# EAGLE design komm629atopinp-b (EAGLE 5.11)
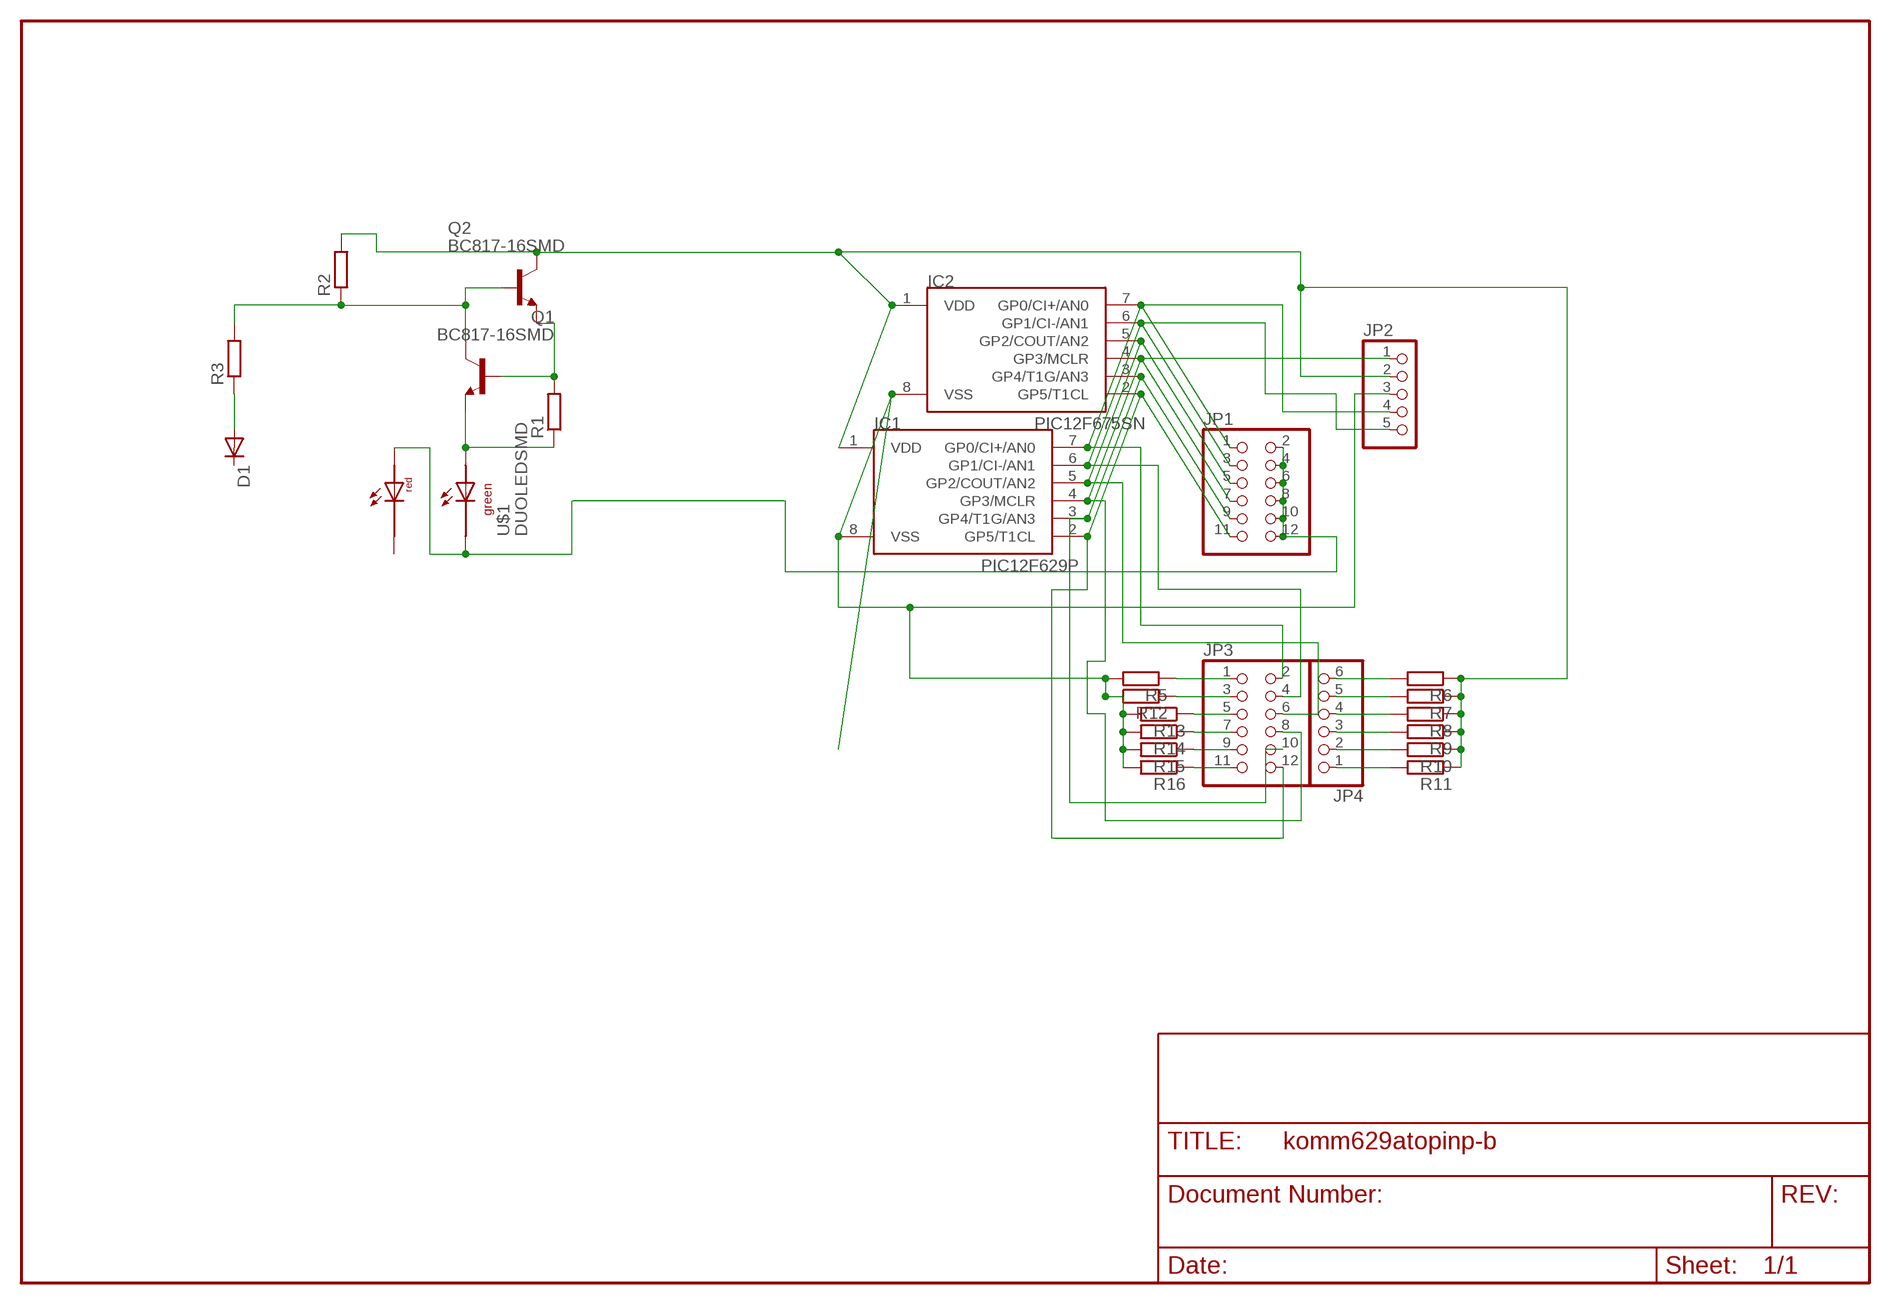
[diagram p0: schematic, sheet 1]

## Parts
D1  DIODE-MINIMELF  [MINIMELF]
IC1  PIC12F629P  [DIL8]
IC2  PIC12F675SN  [SO-08]
JP1  PINHD-2X6  [2X06]
JP2  PINHD-1X5  [1X05]
JP3  PINHD-2X6  [2X06]
JP4  PINHD-1X6  [1X06]
Q1  BC817-16SMD  [SOT23-BEC]
Q2  BC817-16SMD  [SOT23-BEC]
R1  R-EU_R1206  [R1206]
R2  R-EU_R1206  [R1206]
R3  R-EU_R1206  [R1206]
R5  R-EU_R1206  [R1206]
R6  R-EU_R1206  [R1206]
R7  R-EU_R1206  [R1206]
R8  R-EU_R1206  [R1206]
R9  R-EU_R1206  [R1206]
R10  R-EU_R1206  [R1206]
R11  R-EU_R1206  [R1206]
R12  R-EU_R1206  [R1206]
R13  R-EU_R1206  [R1206]
R14  R-EU_R1206  [R1206]
R15  R-EU_R1206  [R1206]
R16  R-EU_R1206  [R1206]
U$1  DUOLEDSMD  [DUOLEDSMD]

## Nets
N$1: IC1.3(GP4/T1G/AN3) IC2.3(GP4/T1G/AN3) JP1.9 JP3.10
N$2: Q1.E R1.1 U$1.AGRN
N$3: Q1.B Q2.E R1.2
N$4: JP1.2 JP1.4 JP1.6 JP1.8 JP1.10 JP1.12 U$1.ARED U$1.CGRN
N$5: IC1.8(VSS) IC2.8(VSS) JP2.3 R5.2 R12.2 R13.2 R14.2 R15.2 R16.2
N$6: IC1.1(VDD) IC2.1(VDD) JP2.2 Q2.C R2.2 R6.1 R7.1 R8.1 R9.1 R10.1 R11.1
N$7: Q1.C Q2.B R2.1 R3.2
N$8: D1.A R3.1
N$9: IC1.2(GP5/T1CL) IC2.2(GP5/T1CL) JP1.11 JP3.12
N$11: IC1.4(GP3/MCLR) IC2.4(GP3/MCLR) JP1.7 JP2.1 JP3.8
N$12: IC1.5(GP2/COUT/AN2) IC2.5(GP2/COUT/AN2) JP1.5 JP3.6
N$13: IC1.6(GP1/CI-/AN1) IC2.6(GP1/CI-/AN1) JP1.3 JP2.5 JP3.4
N$14: IC1.7(GP0/CI+/AN0) IC2.7(GP0/CI+/AN0) JP1.1 JP2.4 JP3.2
N$15: JP4.6 R6.2
N$18: JP3.1 R5.1
N$21: JP3.3 R12.1
N$22: JP3.5 R13.1
N$23: JP3.7 R14.1
N$24: JP3.9 R15.1
N$25: JP3.11 R16.1
N$26: JP4.5 R7.2
N$27: JP4.4 R8.2
N$28: JP4.3 R9.2
N$29: JP4.2 R10.2
N$30: JP4.1 R11.2
Unconnected: D1.C U$1.CRED

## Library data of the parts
D1 = diode:DIODE-: DIODE
IC1 IC2 = microchip-5:PIC12F6*: uPC nW 1k Program Flash memory 2x Timer Comparator 10b A/D converter/ 4xIN
JP1 JP3 = pinhead(2):PINHD-2X6: PIN HEADER
JP2 = pinhead:PINHD-1X5: PIN HEADER
JP4 = pinhead(2):PINHD-1X6: PIN HEADER
Q1 Q2 = transistor-npn:BC817*: NPN Transistor
R1-R3 = rcl:R-EU_: RESISTOR, European symbol
R5-R16 = rcl-2:R-EU_: RESISTOR, European symbol
U$1 = led:DUOLEDSMD

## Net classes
0 default: width 0.3 mm, drill 0.6 mm, clearance 0.2 mm
1 power: width 0.4 mm, drill 0.6 mm, clearance 0.2 mm

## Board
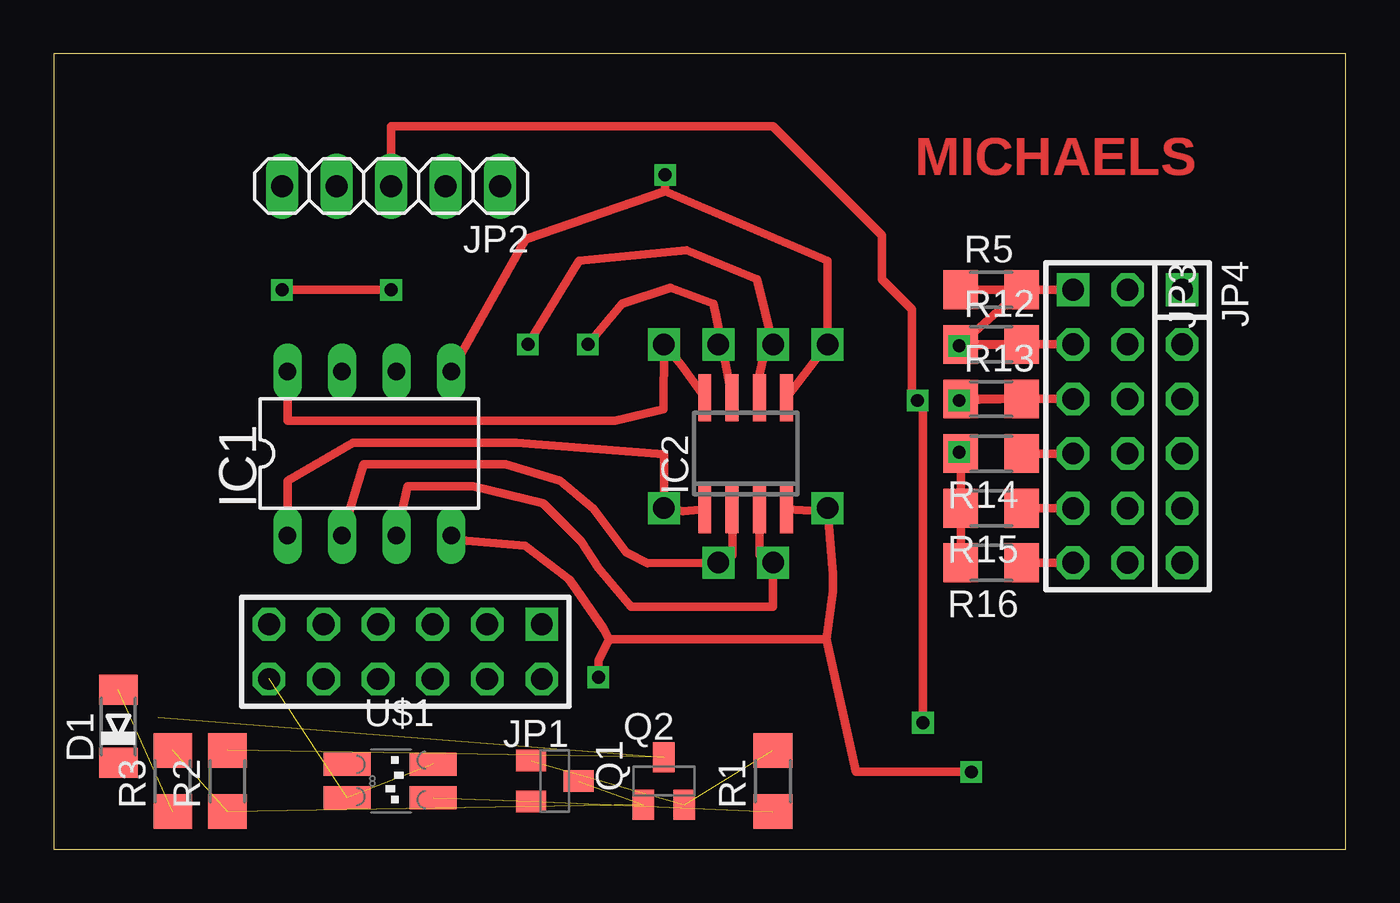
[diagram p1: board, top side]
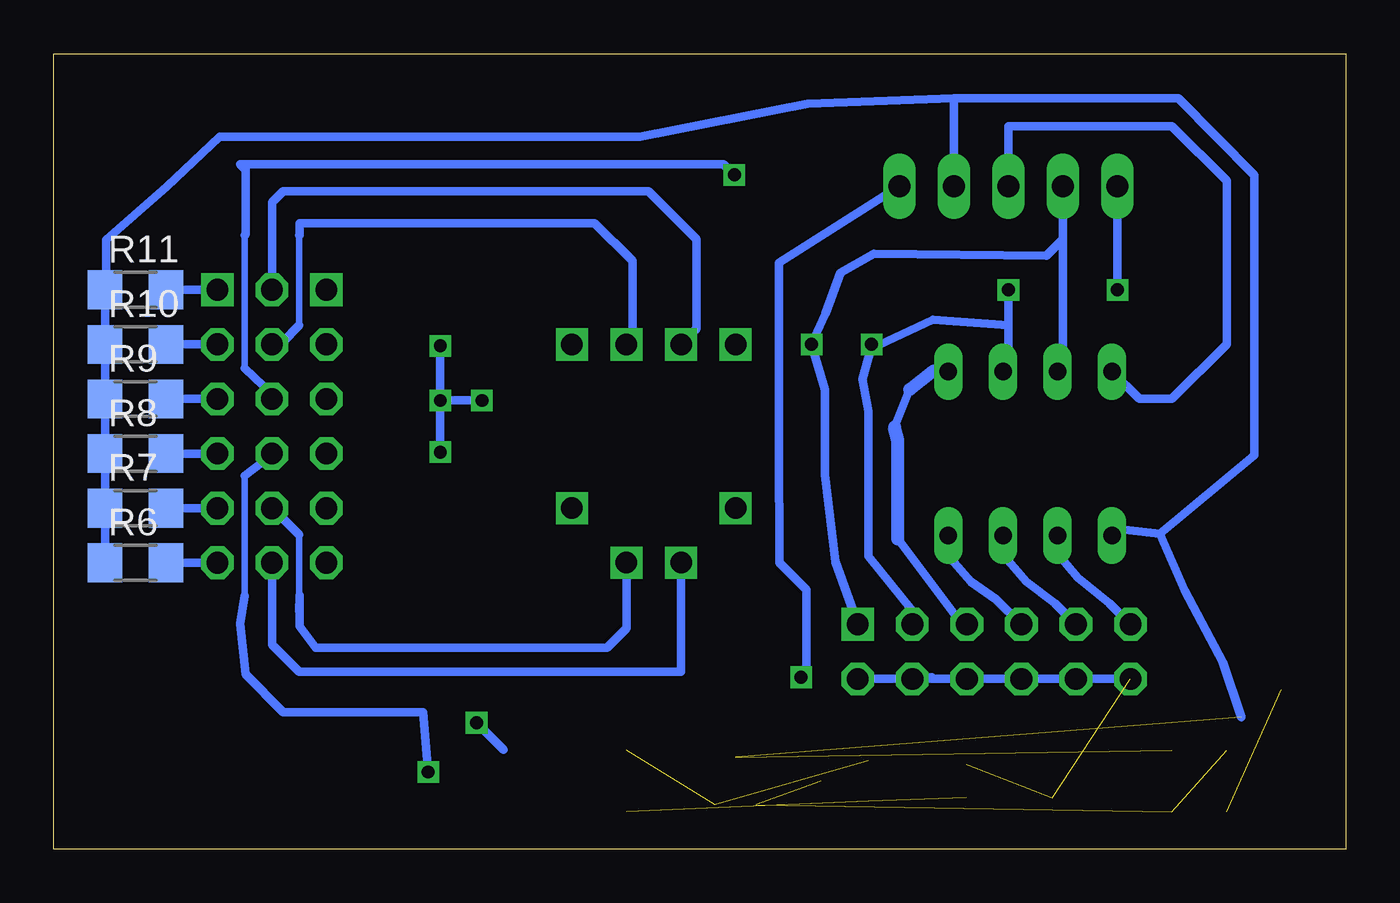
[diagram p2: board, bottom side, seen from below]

Size 60.16 x 37.02 mm. Coordinates in mm from the lower left corner, seen from the top.
Outline: 0,0 60.16,0 60.16,37.02 0,37.02 0,0
Copper layers (1*16): Top 0.035mm / dielectric 1.5mm / Bottom 0.035mm
Design rules "default": minimum track width 10mil, minimum drill 24mil, track to track 8mil, track to pad 8mil, pad to pad 8mil, via to via 8mil, smd to smd 8mil, copper to edge 40mil, drill to drill 8mil, minimum pad ring 10mil, minimum via ring 8mil, stop-mask expansion 4mil, vias tented up to drill 0mil, thermal gap 10mil

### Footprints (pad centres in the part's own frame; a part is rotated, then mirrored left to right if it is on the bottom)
MINIMELF = smd 1.4 x 1.8: A 1.7,0; C -1.7,0
DIL8 = drill 0.813 long: 1 -3.81,-3.81; 2 -1.27,-3.81; 3 1.27,-3.81; 4 3.81,-3.81; 5 3.81,3.81; 6 1.27,3.81; 7 -1.27,3.81; 8 -3.81,3.81
SO-08 = smd 0.6 x 2.2: 1 -1.905,-2.6; 2 -0.635,-2.6; 3 0.635,-2.6; 4 1.905,-2.6; 5 1.905,2.6; 6 0.635,2.6; 7 -0.635,2.6; 8 -1.905,2.6
2X06 = drill 1.016 square: 1 -6.35,-1.27 | drill 1.016 octagon: 2 -6.35,1.27; 3 -3.81,-1.27; 4 -3.81,1.27; 5 -1.27,-1.27; 6 -1.27,1.27; 7 1.27,-1.27; 8 1.27,1.27; 9 3.81,-1.27; 10 3.81,1.27; 11 6.35,-1.27; 12 6.35,1.27
1X05 = drill 1.016 long: 1 -5.08,0; 2 -2.54,0; 3 0,0; 4 2.54,0; 5 5.08,0
1X06 = drill 1.016 square: 1 -6.35,0 | drill 1.016 octagon: 2 -3.81,0; 3 -1.27,0; 4 1.27,0; 5 3.81,0; 6 6.35,0
SOT23-BEC = smd 1 x 1.4: B -0.95,-1.1; C 0,1.1; E 0.95,-1.1
R1206 = smd 1.6 x 1.803: 1 -1.422,0; 2 1.422,0
DUOLEDSMD = smd 1.067 x 2.184: AGRN 0.77,1.95; ARED -0.77,1.95; CGRN 0.77,-2.05; CRED -0.77,-2.05

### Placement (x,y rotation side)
D1  3.01,5.71 90 top
IC1  14.69,18.41 0 top
IC2  32.22,18.41 0 top
JP1  16.37,9.19 180 top
JP2  15.71,30.86 180 top
JP3  48.73,19.68 270 top
JP4  52.54,19.68 270 top
Q1  23.33,3.17 270 top
Q2  28.41,3.17 0 top
R1  33.49,3.17 90 top
R2  8.09,3.17 90 top
R3  5.55,3.17 90 top
R5  43.65,26.03 0 top
R6  56.35,13.33 0 bottom
R7  56.35,15.87 0 bottom
R8  56.35,18.41 0 bottom
R9  56.35,20.95 0 bottom
R10  56.35,23.49 0 bottom
R11  56.35,26.03 0 bottom
R12  43.65,23.49 0 top
R13  43.65,20.95 0 top
R14  43.65,18.41 180 top
R15  43.65,15.87 180 top
R16  43.65,13.33 180 top
U$1  15.71,3.17 270 top

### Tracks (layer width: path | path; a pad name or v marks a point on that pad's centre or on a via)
N$1  (via drill 1)
  Top 0.406: IC2.3 32.86,13.69 v33.49,13.33 33.49,11.28 26.89,11.28 25.36,13.08 24.54,14.33 22.79,16.1 19.52,16.89 16.47,16.89 IC1.3
  Bottom 0.305: 48.73,11.08 48.73,14.63
  Bottom 0.406: IC1.3 16.15,13.93 14.86,12.44 13.54,11.44 JP1.9 | JP3.10 49.96,15.87 48.73,14.63 | 48.73,11.08 48.72,11.82 48.72,10.38 47.97,9.38 34.39,9.38 33.49,10.28 v33.49,13.33
N$2  (2 unrouted)
N$3  (2 unrouted)
N$4  (2 unrouted)
  Bottom 0.406: 19.28,7.98 19.27,8 20.11,8 JP1.4 | JP1.12 JP1.10 JP1.8 JP1.6 JP1.4 | JP1.4 JP1.2
N$5  (via drill 0.6, 1)
  Top 0.406: IC2.8 29.22,22.53 v28.41,23.49 28.39,20.47 26.12,19.93 10.88,19.93 IC1.8 | v42.16,20.88 R13.2 | v40.47,5.88 40.47,20.63 v40.22,20.88 39.97,21.13 39.97,25.13 38.57,26.53 38.57,28.57 33.49,33.65 15.71,33.65 JP2.3 | v42.16,23.42 R12.2 | 42.23,23.49 R5.2 | v42.16,18.48 R14.2 R15.2 R16.2
  Bottom 0.406: IC1.8 9.61,20.95 8.09,20.95 5.55,23.49 5.55,31.11 8.09,33.65 15.71,33.65 JP2.3 | v40.22,20.88 v42.16,20.88 | v40.47,5.88 39.22,4.63 | v42.16,20.88 v42.16,23.42 | v42.16,20.88 v42.16,18.48
N$6  (via drill 1)  (2 unrouted)
  Top 0.406: IC2.1 29.3,15.73 v28.41,15.87 28.41,18.39 21.55,18.92 13.93,18.92 10.88,17.14 IC1.1
  Bottom 0.406: 4.87,6.13 5.74,8.71 7.49,12.02 8.65,14.69 | 8.65,14.69 10.32,14.85 10.63,14.85 IC1.1 | 18.25,34.94 JP2.2 | 18.25,34.94 7.8,34.94 4.26,31.36 4.26,18.33 8.65,14.69 | 18.25,34.94 25.07,34.69 32.86,33.15 52.43,33.15 54.89,30.82 57.72,28.37 57.72,26.08 R11.1 R10.1 R9.1 R8.1 R7.1 R6.1
N$7  (3 unrouted)
N$8  (1 unrouted)
N$9  (via drill 1)
  Top 0.406: IC2.2 31.59,13.69 v30.95,13.33 27.65,13.31 26.64,13.82 25.12,15.84 23.56,17.14 21.04,17.9 14.44,17.9 IC1.2
  Bottom 0.406: IC1.2 13.61,13.99 12.46,12.64 11,11.44 JP1.11 | JP3.12 50,9.52 48.73,8.25 30.95,8.25 v30.95,13.33
N$11  (via drill 0.6, 1)
  Top 0.406: IC2.4 35.66,15.73 v36.03,15.87 36.28,12.81 36.29,12.01 35.97,9.76 | 25.86,9.76 25.6,10.26 24.35,12.06 24,12.56 21.94,14.12 18.69,14.41 IC1.4 | 25.86,9.76 35.97,9.76 | v25.36,8 25.36,8.76 25.86,9.76 | v42.72,3.59 37.35,3.59 35.97,9.76
  Bottom 0.305: 51.27,11.79 51.27,17.38
  Bottom 0.406: IC1.4 18.69,13.87 17.46,12.44 16.28,11.64 JP1.7 | JP2.1 26.39,27.3 26.39,18.92 26.38,13.33 25.11,12.06 25.11,8.25 v25.36,8 | JP3.8 50,18.35 51.27,17.38 | 51.27,11.79 51.47,10.49 51.22,8.13 49.47,6.38 42.97,6.38 v42.72,3.59
N$12  (via drill 0.6, 1)
  Top 0.406: v36.03,23.49 IC2.5 | IC1.5 21.97,28.38 28.47,30.63 | 28.47,30.63 36.03,27.38 | 36.03,27.38 v36.03,23.49 | 28.47,30.63 v28.47,31.38 | 36.03,27.38 v36.03,23.49
  Bottom 0.305: 51.27,28.57 51.27,22.38
  Bottom 0.406: JP1.5 17.88,10.46 20.86,14.44 | 21.01,19.64 20.31,21.39 | JP3.6 50,21.16 51.27,22.38 | 51.27,28.57 51.22,28.62 51.22,31.63 51.47,31.88 28.97,31.88 v28.47,31.38 | 19.19,22.26 18.69,22.03 IC1.5
  Bottom 0.61: 20.31,21.39 19.19,22.26 | 21.01,19.64 20.86,19.04 20.86,14.44
N$13  (via drill 0.6, 1)
  Top 0.406: IC2.6 32.86,22.09 32.99,22.72 v33.49,23.49 32.74,26.53 29.47,27.88 24.47,27.38 v22.08,23.49 | v15.71,26.03 v10.63,26.03
  Bottom 0.305: 48.73,28.57 48.73,24.38
  Bottom 0.406: v10.63,26.03 JP2.5 | 15.71,24.38 15.71,22.47 IC1.6 | 15.71,24.38 v15.71,26.03 | JP1.3 20.18,11.09 22.22,13.63 22.22,20.38 22.51,21.88 22.11,23.29 | 22.11,23.29 19.22,24.63 15.71,24.38 | 22.11,23.29 v22.08,23.49 | JP3.4 49.5,23.6 48.73,24.38 | 48.73,28.57 48.72,28.58 48.72,29.13 34.97,29.13 33.22,27.38 33.22,23.76 v33.49,23.49
N$14  (via drill 0.6, 1)
  Top 0.406: 31.09,23.6 IC2.7 | 31.09,23.6 v30.95,23.49 | 31.09,23.6 30.72,25.38 28.72,26.13 26.47,25.38 v24.87,23.49
  Bottom 0.406: 13.17,28.38 13.17,22.47 IC1.7 | 13.17,28.38 JP2.4 | JP1.1 23.76,13.38 24.26,17.42 24.26,21.38 v24.87,23.49 24.24,24.92 23.54,26.82 21.97,27.71 13.94,27.61 13.17,28.38 | JP3.2 50,30.1 49.47,30.63 32.47,30.63 30.22,28.38 30.22,24.22 v30.95,23.49
N$15
  Bottom 0.406: JP4.6 R6.2
N$18
  Top 0.406: R5.1 JP3.1
N$21
  Top 0.406: R12.1 JP3.3
N$22
  Top 0.406: R13.1 JP3.5
N$23
  Top 0.406: R14.1 JP3.7
N$24
  Top 0.406: R15.1 JP3.9
N$25
  Top 0.406: R16.1 JP3.11
N$26
  Bottom 0.406: JP4.5 R7.2
N$27
  Bottom 0.406: JP4.4 R8.2
N$28
  Bottom 0.406: JP4.3 R9.2
N$29
  Bottom 0.406: JP4.2 R10.2
N$30
  Bottom 0.406: JP4.1 R11.2

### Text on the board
Top: MICHAELS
